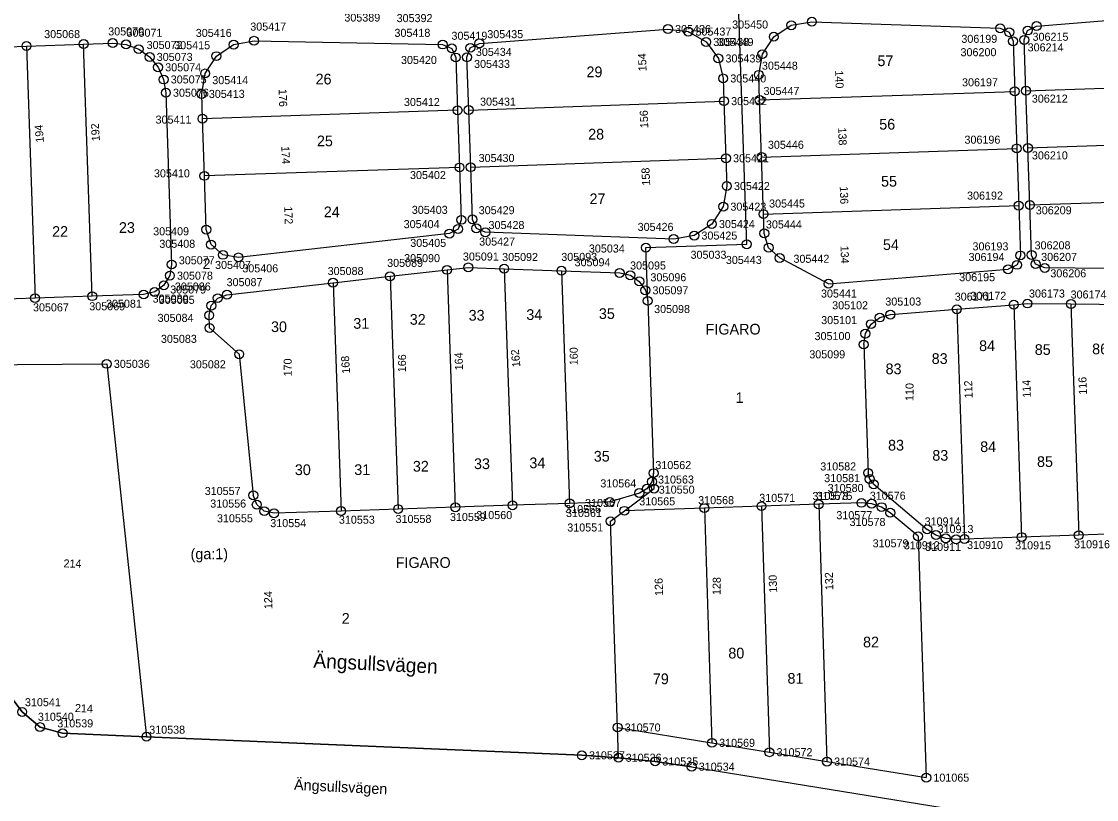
# Model space of a CAD drawing. Extents: x 141995 to 152570, y 6580184 to 6586000.
# Drawn here: x 142125.3 to 142245.6, y 6585201.9 to 6585289.1 of the extents above; entities that cross this region are included whole.
import ezdxf

# ---------------------------------------------------------------- set-up
doc = ezdxf.new("R2010")
doc.units = 0
for name, color, linetype in [('Level 10', 7, 'Continuous'), ('Level 40', 7, 'Continuous'), ('Level 43', 7, 'Continuous'), ('Level 5', 7, 'Continuous'), ('Level 50', 7, 'Continuous'), ('Level 51', 7, 'Continuous'), ('Level 53', 7, 'Continuous'), ('Level 54', 7, 'Continuous'), ('Level 55', 7, 'Continuous'), ('Level 58', 7, 'Continuous'), ('Level 59', 7, 'Continuous'), ('Level 6', 7, 'Continuous'), ('Level 7', 7, 'Continuous')]:
    doc.layers.add(name, color=color, linetype=linetype)

msp = doc.modelspace()

# ---------------------------------------------------------------- linework, layer by layer
at = {"layer": 'Level 10'}
for centre in [(142213.79, 6585289.06), (142197.68, 6585288.25), (142199.96, 6585287.96), (142211.49, 6585288.67), (142234.87, 6585288.33), (142235.88, 6585287.89), (142237.94, 6585288.08), (142238.94, 6585288.58), (142132.28, 6585286.56), (142135.54, 6585286.67), (142137.03, 6585286.52), (142149.07, 6585286.5), (142151.35, 6585286.93), (142172.46, 6585286.51), (142176.57, 6585286.64), (142201.95, 6585286.8), (142209.53, 6585287.38), (142236.31, 6585286.88), (142237.56, 6585287.03), (142125.88, 6585286.34), (142138.44, 6585285.99), (142173.49, 6585286.08), (142175.56, 6585286.14), (142208.25, 6585285.43), (142139.66, 6585285.12), (142147.14, 6585285.21), (142173.93, 6585285.06), (142175.18, 6585285.09), (142203.32, 6585284.95), (142140.61, 6585283.96), (142145.88, 6585283.27), (142207.85, 6585283.12), (142141.23, 6585282.59), (142203.86, 6585282.71), (142141.48, 6585281.11), (142145.49, 6585280.98), (142236.5, 6585281.26), (142237.75, 6585281.33), (142203.95, 6585280.17), (142207.94, 6585280.3), (142145.58, 6585278.2), (142174.13, 6585279.14), (142175.38, 6585279.17), (142236.72, 6585274.87), (142237.97, 6585274.93), (142204.17, 6585273.77), (142208.16, 6585273.91), (142174.35, 6585272.74), (142175.6, 6585272.77), (142145.8, 6585271.8), (142204.27, 6585270.66), (142236.94, 6585268.47), (142238.19, 6585268.54), (142203.87, 6585268.35), (142208.38, 6585267.51), (142174.55, 6585266.87), (142175.8, 6585266.92), (142202.59, 6585266.4), (142146, 6585265.78), (142173.22, 6585265.33), (142174.19, 6585265.84), (142176.24, 6585265.92), (142177.24, 6585265.48), (142200.63, 6585265.11), (142208.46, 6585265.36), (142146.54, 6585264.1), (142195.21, 6585263.76), (142198.32, 6585264.72), (142206.5, 6585264.14), (142208.95, 6585263.75), (142147.87, 6585262.95), (142149.61, 6585262.66), (142210.19, 6585262.6), (142237.13, 6585262.88), (142238.38, 6585262.93), (142142.13, 6585261.87), (142172.95, 6585261.27), (142175.34, 6585261.54), (142179.35, 6585261.4), (142235.75, 6585261.34), (142236.75, 6585261.83), (142238.83, 6585261.91), (142239.86, 6585261.48), (142141.93, 6585260.62), (142166.57, 6585260.55), (142185.76, 6585261.17), (142192.28, 6585260.93), (142193.47, 6585260.66), (142194.47, 6585259.98), (142140.23, 6585258.8), (142141.26, 6585259.54), (142160.19, 6585259.83), (142195.15, 6585258.98), (142215.65, 6585259.72), (142126.84, 6585258.1), (142133.24, 6585258.32), (142138.99, 6585258.51), (142147.29, 6585258.1), (142148.32, 6585258.49), (142195.42, 6585257.8), (142146.56, 6585257.26), (142230.01, 6585256.86), (142236.39, 6585257.37), (142237.92, 6585257.5), (142242.79, 6585257.45), (142146.33, 6585256.18), (142220.41, 6585255.19), (142221.39, 6585255.93), (142222.58, 6585256.26), (142146.37, 6585254.76), (142219.78, 6585254.13), (142219.59, 6585252.91), (142149.69, 6585251.82), (142134.86, 6585250.74), (142196.07, 6585238.5), (142220.09, 6585238.53), (142195.89, 6585237.54), (142220.26, 6585237.83), (142220.71, 6585237.25), (142151.27, 6585236.02), (142194.48, 6585236.27), (142195.33, 6585236.75), (142196.13, 6585236.77), (142151.66, 6585234.97), (142180.28, 6585234.9), (142186.67, 6585235.11), (142191.18, 6585235.27), (142208.15, 6585234.8), (142214.55, 6585235.01), (142219.34, 6585235.17), (142220.49, 6585235.07), (142152.5, 6585234.24), (142153.59, 6585234), (142161.09, 6585234.25), (142167.48, 6585234.47), (142173.88, 6585234.68), (142192.81, 6585234.28), (142201.76, 6585234.58), (142221.59, 6585234.69), (142222.56, 6585234.06), (142191.25, 6585233.11), (142225.68, 6585231.43), (142226.7, 6585232.2), (142227.68, 6585231.56), (142228.77, 6585231.19), (142230.87, 6585231.12), (142237.27, 6585231.33), (142243.66, 6585231.55), (142229.93, 6585231.08), (142125.4, 6585211.75), (142127.4, 6585210.05), (142192.04, 6585210.01), (142129.93, 6585209.37), (142139.31, 6585208.97), (142202.61, 6585208.29), (142209.04, 6585207.24), (142188.04, 6585206.89), (142192.15, 6585206.62), (142196.25, 6585206.2), (142215.48, 6585206.19), (142200.33, 6585205.62), (142226.59, 6585204.39)]:
    msp.add_circle(centre, 0.5, dxfattribs=at)
at = {"layer": 'Level 5'}
for points in [[(142125.4, 6585211.75), (142119.26, 6585219.85)], [(142127.4, 6585210.05), (142125.4, 6585211.75)], [(142129.93, 6585209.37), (142127.4, 6585210.05)], [(142139.31, 6585208.97), (142129.93, 6585209.37)], [(142188.04, 6585206.89), (142139.31, 6585208.97)], [(142192.15, 6585206.62), (142188.04, 6585206.89)], [(142196.25, 6585206.2), (142192.15, 6585206.62)], [(142200.33, 6585205.62), (142196.25, 6585206.2)], [(142200.33, 6585205.62), (142366.8, 6585178.55)]]:
    msp.add_lwpolyline(points, dxfattribs=at)
at = {"layer": 'Level 6'}
for points in [[(142119.26, 6585219.85), (142125.4, 6585211.75), (142127.4, 6585210.05), (142129.93, 6585209.37), (142139.31, 6585208.97), (142188.04, 6585206.89), (142192.15, 6585206.62), (142196.25, 6585206.2), (142200.33, 6585205.62)], [(142200.33, 6585205.62), (142366.8, 6585178.55)]]:
    msp.add_lwpolyline(points, dxfattribs=at)
at = {"layer": 'Level 7'}
for points in [[(142206.5, 6585264.14), (142205.58, 6585290.99)], [(142238.94, 6585288.58), (142260.02, 6585290.29)], [(142176.57, 6585286.64), (142197.68, 6585288.25)], [(142197.68, 6585288.25), (142199.96, 6585287.96)], [(142209.53, 6585287.38), (142211.49, 6585288.67)], [(142211.49, 6585288.67), (142213.79, 6585289.06)], [(142213.79, 6585289.06), (142234.87, 6585288.33)], [(142234.87, 6585288.33), (142235.88, 6585287.89)], [(142237.94, 6585288.08), (142238.94, 6585288.58)], [(142199.96, 6585287.96), (142201.95, 6585286.8)], [(142208.25, 6585285.43), (142209.53, 6585287.38)], [(142235.88, 6585287.89), (142236.31, 6585286.88)], [(142237.56, 6585287.03), (142237.94, 6585288.08)], [(142237.75, 6585281.33), (142237.56, 6585287.03)], [(142119.48, 6585286.12), (142125.88, 6585286.34)], [(142125.88, 6585286.34), (142132.28, 6585286.56)], [(142125.88, 6585286.34), (142126.84, 6585258.1)], [(142132.28, 6585286.56), (142135.54, 6585286.67)], [(142133.24, 6585258.32), (142132.28, 6585286.56)], [(142135.54, 6585286.67), (142137.03, 6585286.52)], [(142137.03, 6585286.52), (142138.44, 6585285.99)], [(142138.44, 6585285.99), (142139.66, 6585285.12)], [(142147.14, 6585285.21), (142149.07, 6585286.5)], [(142149.07, 6585286.5), (142151.35, 6585286.93)], [(142151.35, 6585286.93), (142172.46, 6585286.51)], [(142172.46, 6585286.51), (142173.49, 6585286.08)], [(142173.49, 6585286.08), (142173.93, 6585285.06)], [(142175.18, 6585285.09), (142175.56, 6585286.14)], [(142175.56, 6585286.14), (142176.57, 6585286.64)], [(142201.95, 6585286.8), (142203.32, 6585284.95)], [(142236.31, 6585286.88), (142236.5, 6585281.26)], [(142139.66, 6585285.12), (142140.61, 6585283.96)], [(142145.88, 6585283.27), (142147.14, 6585285.21)], [(142173.93, 6585285.06), (142174.13, 6585279.14)], [(142175.38, 6585279.17), (142175.18, 6585285.09)], [(142203.32, 6585284.95), (142203.86, 6585282.71)], [(142207.85, 6585283.12), (142208.25, 6585285.43)], [(142140.61, 6585283.96), (142141.23, 6585282.59)], [(142141.23, 6585282.59), (142141.48, 6585281.11)], [(142145.49, 6585280.98), (142145.88, 6585283.27)], [(142203.86, 6585282.71), (142203.95, 6585280.17)], [(142207.94, 6585280.3), (142207.85, 6585283.12)], [(142237.75, 6585281.33), (142266.32, 6585282.3)], [(142141.48, 6585281.11), (142142.13, 6585261.87)], [(142145.58, 6585278.2), (142145.49, 6585280.98)], [(142207.94, 6585280.3), (142236.5, 6585281.26)], [(142236.5, 6585281.26), (142236.72, 6585274.87)], [(142237.97, 6585274.93), (142237.75, 6585281.33)], [(142175.38, 6585279.17), (142203.95, 6585280.17)], [(142203.95, 6585280.17), (142204.17, 6585273.77)], [(142208.16, 6585273.91), (142207.94, 6585280.3)], [(142174.13, 6585279.14), (142145.58, 6585278.2)], [(142174.13, 6585279.14), (142174.35, 6585272.74)], [(142175.6, 6585272.77), (142175.38, 6585279.17)], [(142145.8, 6585271.8), (142145.58, 6585278.2)], [(142237.97, 6585274.93), (142266.53, 6585275.9)], [(142238.19, 6585268.54), (142237.97, 6585274.93)], [(142175.6, 6585272.77), (142204.17, 6585273.77)], [(142204.17, 6585273.77), (142204.27, 6585270.66)], [(142208.16, 6585273.91), (142236.72, 6585274.87)], [(142208.38, 6585267.51), (142208.16, 6585273.91)], [(142236.72, 6585274.87), (142236.94, 6585268.47)], [(142174.35, 6585272.74), (142145.8, 6585271.8)], [(142174.35, 6585272.74), (142174.55, 6585266.87)], [(142175.8, 6585266.92), (142175.6, 6585272.77)], [(142146, 6585265.78), (142145.8, 6585271.8)], [(142204.27, 6585270.66), (142203.87, 6585268.35)], [(142238.19, 6585268.54), (142266.75, 6585269.5)], [(142203.87, 6585268.35), (142202.59, 6585266.4)], [(142208.38, 6585267.51), (142236.94, 6585268.47)], [(142236.94, 6585268.47), (142237.13, 6585262.88)], [(142238.38, 6585262.93), (142238.19, 6585268.54)], [(142174.55, 6585266.87), (142174.19, 6585265.84)], [(142176.24, 6585265.92), (142175.8, 6585266.92)], [(142208.46, 6585265.36), (142208.38, 6585267.51)], [(142146.54, 6585264.1), (142146, 6585265.78)], [(142173.22, 6585265.33), (142149.61, 6585262.66)], [(142174.19, 6585265.84), (142173.22, 6585265.33)], [(142177.24, 6585265.48), (142176.24, 6585265.92)], [(142198.32, 6585264.72), (142177.24, 6585265.48)], [(142202.59, 6585266.4), (142200.63, 6585265.11)], [(142208.95, 6585263.75), (142208.46, 6585265.36)], [(142147.87, 6585262.95), (142146.54, 6585264.1)], [(142195.21, 6585263.76), (142206.5, 6585264.14)], [(142200.63, 6585265.11), (142198.32, 6585264.72)], [(142149.61, 6585262.66), (142147.87, 6585262.95)], [(142195.42, 6585257.8), (142195.21, 6585263.76)], [(142210.19, 6585262.6), (142208.95, 6585263.75)], [(142237.13, 6585262.88), (142236.75, 6585261.83)], [(142238.83, 6585261.91), (142238.38, 6585262.93)], [(142142.13, 6585261.87), (142141.93, 6585260.62)], [(142215.65, 6585259.72), (142210.19, 6585262.6)], [(142236.75, 6585261.83), (142235.75, 6585261.34)], [(142239.86, 6585261.48), (142238.83, 6585261.91)], [(142141.93, 6585260.62), (142141.26, 6585259.54)], [(142160.19, 6585259.83), (142166.57, 6585260.55)], [(142166.57, 6585260.55), (142172.95, 6585261.27)], [(142166.57, 6585260.55), (142167.48, 6585234.47)], [(142172.95, 6585261.27), (142175.34, 6585261.54)], [(142172.95, 6585261.27), (142173.88, 6585234.68)], [(142175.34, 6585261.54), (142179.35, 6585261.4)], [(142179.35, 6585261.4), (142185.76, 6585261.17)], [(142179.35, 6585261.4), (142180.28, 6585234.9)], [(142185.76, 6585261.17), (142192.28, 6585260.93)], [(142185.76, 6585261.17), (142186.67, 6585235.11)], [(142192.28, 6585260.93), (142193.47, 6585260.66)], [(142193.47, 6585260.66), (142194.47, 6585259.98)], [(142215.65, 6585259.72), (142235.75, 6585261.34)], [(142263.64, 6585261.25), (142239.86, 6585261.48)], [(142141.26, 6585259.54), (142140.23, 6585258.8)], [(142148.32, 6585258.49), (142160.19, 6585259.83)], [(142160.19, 6585259.83), (142161.09, 6585234.25)], [(142194.47, 6585259.98), (142195.15, 6585258.98)], [(142126.84, 6585258.1), (142120.44, 6585257.88)], [(142133.24, 6585258.32), (142126.84, 6585258.1)], [(142138.99, 6585258.51), (142133.24, 6585258.32)], [(142140.23, 6585258.8), (142138.99, 6585258.51)], [(142146.56, 6585257.26), (142147.29, 6585258.1)], [(142147.29, 6585258.1), (142148.32, 6585258.49)], [(142195.15, 6585258.98), (142195.42, 6585257.8)], [(142146.33, 6585256.18), (142146.56, 6585257.26)], [(142195.42, 6585257.8), (142196.07, 6585238.5)], [(142222.58, 6585256.26), (142230.01, 6585256.86)], [(142230.01, 6585256.86), (142236.39, 6585257.37)], [(142230.01, 6585256.86), (142230.87, 6585231.12)], [(142236.39, 6585257.37), (142237.92, 6585257.5)], [(142236.39, 6585257.37), (142237.27, 6585231.33)], [(142237.92, 6585257.5), (142242.79, 6585257.45)], [(142242.79, 6585257.45), (142249.2, 6585257.39)], [(142242.79, 6585257.45), (142243.66, 6585231.55)], [(142146.37, 6585254.76), (142146.33, 6585256.18)], [(142220.41, 6585255.19), (142221.39, 6585255.93)], [(142221.39, 6585255.93), (142222.58, 6585256.26)], [(142149.69, 6585251.82), (142146.37, 6585254.76)], [(142219.78, 6585254.13), (142220.41, 6585255.19)], [(142219.59, 6585252.91), (142219.78, 6585254.13)], [(142219.59, 6585252.91), (142220.09, 6585238.53)], [(142149.69, 6585251.82), (142151.27, 6585236.02)], [(142104.84, 6585250.52), (142134.86, 6585250.74)], [(142134.86, 6585250.74), (142139.31, 6585208.97)], [(142196.07, 6585238.5), (142195.89, 6585237.54)], [(142196.13, 6585236.77), (142196.07, 6585238.5)], [(142220.26, 6585237.83), (142220.09, 6585238.53)], [(142220.71, 6585237.25), (142220.26, 6585237.83)], [(142192.81, 6585234.28), (142196.13, 6585236.77)], [(142195.33, 6585236.75), (142194.48, 6585236.27)], [(142195.89, 6585237.54), (142195.33, 6585236.75)], [(142220.71, 6585237.25), (142226.7, 6585232.2)], [(142151.66, 6585234.97), (142151.27, 6585236.02)], [(142191.18, 6585235.27), (142186.67, 6585235.11)], [(142194.48, 6585236.27), (142191.18, 6585235.27)], [(142152.5, 6585234.24), (142151.66, 6585234.97)], [(142153.59, 6585234), (142152.5, 6585234.24)], [(142161.09, 6585234.25), (142153.59, 6585234)], [(142167.48, 6585234.47), (142161.09, 6585234.25)], [(142173.88, 6585234.68), (142167.48, 6585234.47)], [(142180.28, 6585234.9), (142173.88, 6585234.68)], [(142186.67, 6585235.11), (142180.28, 6585234.9)], [(142191.25, 6585233.11), (142192.81, 6585234.28)], [(142201.76, 6585234.58), (142192.81, 6585234.28)], [(142208.15, 6585234.8), (142201.76, 6585234.58)], [(142201.76, 6585234.58), (142202.61, 6585208.29)], [(142214.55, 6585235.01), (142208.15, 6585234.8)], [(142208.15, 6585234.8), (142209.04, 6585207.24)], [(142219.34, 6585235.17), (142214.55, 6585235.01)], [(142214.55, 6585235.01), (142215.48, 6585206.19)], [(142220.49, 6585235.07), (142219.34, 6585235.17)], [(142221.59, 6585234.69), (142220.49, 6585235.07)], [(142222.56, 6585234.06), (142221.59, 6585234.69)], [(142225.68, 6585231.43), (142222.56, 6585234.06)], [(142192.04, 6585210.01), (142191.25, 6585233.11)], [(142227.68, 6585231.56), (142226.7, 6585232.2)], [(142250.06, 6585231.77), (142243.66, 6585231.55)], [(142225.68, 6585231.43), (142226.59, 6585204.39)], [(142228.77, 6585231.19), (142227.68, 6585231.56)], [(142229.93, 6585231.08), (142228.77, 6585231.19)], [(142230.87, 6585231.12), (142229.93, 6585231.08)], [(142237.27, 6585231.33), (142230.87, 6585231.12)], [(142243.66, 6585231.55), (142237.27, 6585231.33)], [(142192.15, 6585206.62), (142192.04, 6585210.01)], [(142192.04, 6585210.01), (142202.61, 6585208.29)], [(142202.61, 6585208.29), (142209.04, 6585207.24)], [(142209.04, 6585207.24), (142215.48, 6585206.19)], [(142215.48, 6585206.19), (142226.59, 6585204.39)]]:
    msp.add_lwpolyline(points, dxfattribs=at)

# ---------------------------------------------------------------- texts
at = {"layer": 'Level 40'}
msp.add_text('Ängsullsvägen', height=1.2, rotation=357.1617, dxfattribs=at).set_placement((142155.81, 6585203.03))
at = {"layer": 'Level 43'}
msp.add_text('Ängsullsvägen', height=1.6, rotation=357.1617, dxfattribs=at).set_placement((142157.97, 6585216.72))
at = {"layer": 'Level 50'}
msp.add_text('FIGARO', height=1.2, rotation=0.0526, dxfattribs=at).set_placement((142201.9, 6585254.02))
at = {"layer": 'Level 51'}
for s, p in [('57', (142221.13, 6585284.09)), ('29', (142188.56, 6585282.85)), ('26', (142158.24, 6585282.04)), ('56', (142221.33, 6585276.98)), ('25', (142158.39, 6585275.11)), ('28', (142188.75, 6585275.87)), ('55', (142221.53, 6585270.59)), ('27', (142188.9, 6585268.63)), ('24', (142159.16, 6585267.16)), ('23', (142136.23, 6585265.41)), ('22', (142128.75, 6585264.97)), ('54', (142221.74, 6585263.49)), ('2', (142145.59, 6585261.35)), ('34', (142181.83, 6585255.66)), ('35', (142189.95, 6585255.77)), ('31', (142162.46, 6585254.67)), ('32', (142168.78, 6585255.12)), ('33', (142175.37, 6585255.58)), ('30', (142153.25, 6585254.3)), ('85', (142238.74, 6585251.74)), ('83', (142222.04, 6585249.58)), ('1', (142205.25, 6585246.36)), ('84', (142232.63, 6585240.86)), ('(ga:1)', (142144.25, 6585228.86)), ('2', (142161.17, 6585221.63)), ('82', (142219.52, 6585218.98)), ('80', (142204.44, 6585217.74)), ('79', (142195.99, 6585214.86)), ('81', (142211.06, 6585214.91))]:
    msp.add_text(s, height=1.2, rotation=0.0526, dxfattribs=at).set_placement(p)
at = {"layer": 'Level 53'}
for s, p in [('305389', (142161.46, 6585289.08)), ('305392', (142167.31, 6585289.02)), ('305070', (142135.03, 6585287.53)), ('305071', (142137.08, 6585287.38)), ('305416', (142144.83, 6585287.36)), ('305417', (142150.93, 6585288.07)), ('305418', (142167.07, 6585287.37)), ('305436', (142198.48, 6585287.8)), ('305437', (142200.76, 6585287.51)), ('305450', (142204.87, 6585288.3)), ('305068', (142127.86, 6585287.23)), ('305419', (142173.45, 6585287.04)), ('305435', (142177.46, 6585287.22)), ('305438', (142202.75, 6585286.35)), ('305449', (142203.24, 6585286.34)), ('306199', (142230.52, 6585286.7)), ('306215', (142238.49, 6585286.93)), ('305072', (142139.33, 6585286.01)), ('305415', (142142.42, 6585285.98)), ('305434', (142176.18, 6585285.23)), ('306200', (142230.43, 6585285.2)), ('306214', (142237.94, 6585285.74)), ('305073', (142140.46, 6585284.67)), ('305420', (142167.8, 6585284.33)), ('305433', (142175.98, 6585283.89)), ('305439', (142204.12, 6585284.5)), ('305448', (142208.2, 6585283.69)), ('305074', (142141.41, 6585283.51)), ('305075', (142142.03, 6585282.15)), ('305414', (142146.68, 6585282.07)), ('305440', (142204.66, 6585282.26)), ('306197', (142230.6, 6585281.83)), ('305076', (142142.28, 6585280.66)), ('305413', (142146.29, 6585280.53)), ('305447', (142208.38, 6585280.86)), ('305412', (142168.13, 6585279.62)), ('305431', (142176.65, 6585279.66)), ('305432', (142204.75, 6585279.72)), ('306212', (142238.41, 6585280)), ('305411', (142140.33, 6585277.65)), ('306196', (142230.87, 6585275.4)), ('305446', (142208.87, 6585274.83)), ('305430', (142176.49, 6585273.35)), ('305421', (142204.97, 6585273.32)), ('306210', (142238.42, 6585273.64)), ('305410', (142140.15, 6585271.63)), ('305402', (142168.81, 6585271.44)), ('305422', (142205.07, 6585270.21)), ('305445', (142209, 6585268.25)), ('306192', (142231.16, 6585269.14)), ('305403', (142169.01, 6585267.54)), ('305429', (142176.5, 6585267.5)), ('305423', (142204.67, 6585267.9)), ('306209', (142238.85, 6585267.49)), ('305404', (142168.1, 6585265.94)), ('305428', (142177.6, 6585265.84)), ('305426', (142194.29, 6585265.63)), ('305424', (142203.39, 6585265.95)), ('305444', (142208.65, 6585265.91)), ('305409', (142140.06, 6585265.14)), ('305425', (142201.43, 6585264.66)), ('305408', (142140.75, 6585263.74)), ('305405', (142168.84, 6585263.84)), ('305427', (142176.55, 6585263.99)), ('305034', (142188.83, 6585263.21)), ('306193', (142231.77, 6585263.45)), ('306208', (142238.72, 6585263.57)), ('305090', (142168.15, 6585262.13)), ('305091', (142174.73, 6585262.31)), ('305092', (142179.12, 6585262.26)), ('305093', (142185.74, 6585262.27)), ('305033', (142200.21, 6585262.51)), ('305442', (142211.73, 6585262.06)), ('306194', (142231.33, 6585262.26)), ('306207', (142239.45, 6585262.27)), ('305077', (142142.93, 6585261.89)), ('305407', (142146.99, 6585261.37)), ('305406', (142150.04, 6585260.99)), ('305089', (142166.25, 6585261.6)), ('305094', (142187.23, 6585261.67)), ('305095', (142193.44, 6585261.31)), ('305443', (142204.16, 6585261.93)), ('305078', (142142.73, 6585260.17)), ('305088', (142159.59, 6585260.69)), ('305096', (142195.72, 6585259.99)), ('306195', (142230.28, 6585260)), ('306206', (142240.48, 6585260.43)), ('305079', (142141.97, 6585258.62)), ('305086', (142142.49, 6585258.95)), ('305087', (142148.28, 6585259.44)), ('305097', (142195.95, 6585258.53)), ('305080', (142140, 6585257.6)), ('305085', (142140.69, 6585257.46)), ('305441', (142214.81, 6585258.17)), ('305103', (142222.01, 6585257.27)), ('306171', (142229.78, 6585257.82)), ('306172', (142231.53, 6585257.91)), ('306173', (142238.09, 6585258.17)), ('306174', (142242.75, 6585258.06)), ('305067', (142126.61, 6585256.62)), ('305069', (142132.91, 6585256.74)), ('305081', (142134.78, 6585257.03)), ('305098', (142196.13, 6585256.43)), ('305102', (142216.06, 6585256.85)), ('305084', (142140.56, 6585255.44)), ('305101', (142214.83, 6585255.19)), ('305083', (142140.93, 6585253.09)), ('305100', (142214.09, 6585253.4)), ('305099', (142213.5, 6585251.36)), ('305036', (142135.66, 6585250.29)), ('305082', (142144.17, 6585250.24)), ('310562', (142196.27, 6585238.95)), ('310582', (142214.73, 6585238.8)), ('310564', (142190.11, 6585236.9)), ('310563', (142196.57, 6585237.33)), ('310581', (142215.17, 6585237.49)), ('310557', (142145.83, 6585236.05)), ('310550', (142196.65, 6585236.2)), ('310573', (142213.85, 6585235.49)), ('310575', (142214.31, 6585235.5)), ('310580', (142215.56, 6585236.38)), ('310576', (142220.27, 6585235.52)), ('310556', (142146.45, 6585234.64)), ('310567', (142188.4, 6585234.71)), ('310565', (142194.47, 6585234.89)), ('310568', (142201.06, 6585235.02)), ('310571', (142207.9, 6585235.28)), ('310559', (142173.28, 6585233.14)), ('310560', (142176.23, 6585233.35)), ('310566', (142186.18, 6585234.03)), ('310561', (142186.27, 6585233.58)), ('310577', (142216.53, 6585233.34)), ('310555', (142147.2, 6585232.99)), ('310554', (142153.17, 6585232.45)), ('310553', (142160.85, 6585232.83)), ('310558', (142167.19, 6585232.92)), ('310551', (142186.41, 6585231.96)), ('310578', (142218.01, 6585232.58)), ('310914', (142226.41, 6585232.64)), ('310913', (142227.86, 6585231.78)), ('310579', (142220.59, 6585230.19)), ('310912', (142224.08, 6585229.97)), ('310911', (142226.47, 6585229.79)), ('310910', (142231.16, 6585230)), ('310915', (142236.54, 6585229.96)), ('310916', (142243.14, 6585230.08)), ('310541', (142125.71, 6585212.39)), ('310540', (142127.16, 6585210.76)), ('310539', (142129.33, 6585210.02)), ('310538', (142139.62, 6585209.31)), ('310570', (142192.84, 6585209.56)), ('310569', (142203.41, 6585207.84)), ('310572', (142209.84, 6585206.79)), ('310537', (142188.84, 6585206.44)), ('310536', (142192.95, 6585206.17)), ('310535', (142197.05, 6585205.75)), ('310574', (142216.28, 6585205.74)), ('310534', (142201.13, 6585205.17)), ('101065', (142227.39, 6585203.94))]:
    msp.add_text(s, height=0.9, rotation=0.0526, dxfattribs=at).set_placement(p)
at = {"layer": 'Level 54'}
for s, rotation, p in [('154', 91.9187, (142195.29, 6585283.53)), ('140', 271.9497, (142216.39, 6585283.59)), ('176', 271.9457, (142154.1, 6585281.52)), ('156', 91.9187, (142195.48, 6585277.16)), ('194', 94.5738, (142127.84, 6585275.56)), ('192', 93.8978, (142134.11, 6585275.71)), ('138', 271.9497, (142216.73, 6585277.2)), ('174', 271.9457, (142154.41, 6585275.12)), ('158', 92.8238, (142195.7, 6585270.73)), ('136', 271.9497, (142216.91, 6585270.62)), ('172', 271.9457, (142154.73, 6585268.37)), ('134', 271.9497, (142216.99, 6585263.96)), ('162', 95.4178, (142181.17, 6585250.41)), ('160', 89.9337, (142187.58, 6585250.59)), ('170', 90.5777, (142155.58, 6585249.34)), ('168', 93.9628, (142162.11, 6585249.67)), ('166', 89.4237, (142168.35, 6585249.8)), ('164', 92.0047, (142174.75, 6585250.03)), ('110', 89.5357, (142225.16, 6585246.58)), ('112', 91.9367, (142231.79, 6585246.89)), ('114', 91.9367, (142238.3, 6585246.96)), ('116', 91.9367, (142244.58, 6585247.3)), ('214', 358.9376, (142130.02, 6585227.94)), ('128', 88.8817, (142203.56, 6585224.84)), ('130', 91.8507, (142209.91, 6585225.12)), ('132', 91.8507, (142216.2, 6585225.41)), ('126', 91.8507, (142197.14, 6585224.76)), ('124', 91.6227, (142153.41, 6585223.28))]:
    msp.add_text(s, height=0.9, rotation=rotation, dxfattribs=at).set_placement(p)
at = {"layer": 'Level 55'}
msp.add_text('214', height=0.9, rotation=357.5106, dxfattribs=at).set_placement((142131.29, 6585211.75))
at = {"layer": 'Level 58'}
msp.add_text('FIGARO', height=1.2, rotation=0.0526, dxfattribs=at).set_placement((142167.21, 6585227.88))
at = {"layer": 'Level 59'}
for s, p in [('84', (142232.51, 6585252.17)), ('86', (142245.16, 6585251.81)), ('83', (142227.2, 6585250.73)), ('83', (142222.32, 6585241.03)), ('33', (142175.97, 6585238.95)), ('34', (142182.17, 6585239.05)), ('35', (142189.38, 6585239.79)), ('83', (142227.27, 6585239.89)), ('85', (142238.99, 6585239.19)), ('30', (142155.92, 6585238.28)), ('31', (142162.57, 6585238.29)), ('32', (142169.13, 6585238.67))]:
    msp.add_text(s, height=1.2, rotation=0.0526, dxfattribs=at).set_placement(p)

doc.saveas('drawing.dxf')
